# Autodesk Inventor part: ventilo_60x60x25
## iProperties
Created: 2011-01
Part Number: ventilo_60x60x25
Document SubType Name: Modeling
Designer: eric
Density: 1 g/cm^3
Mass: 54.508 g
Surface Area: 203.469 cm^2
Volume: 54.508 cm^3
Author: eric
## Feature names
1. Base1
